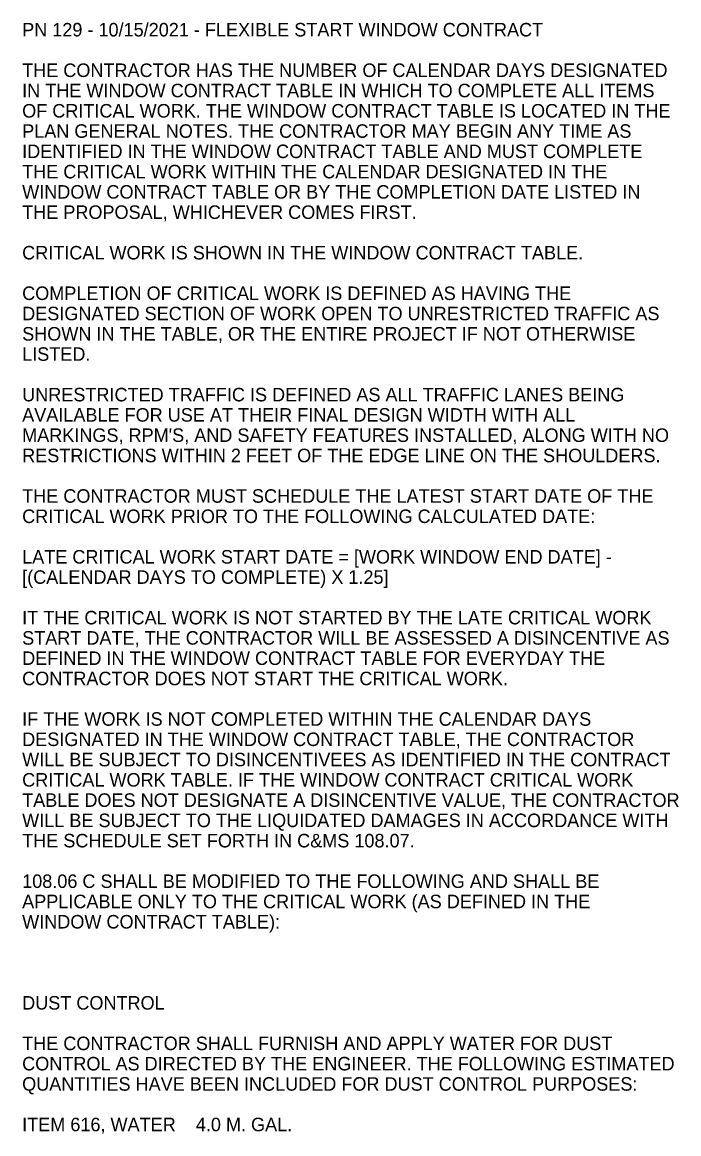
# Model space of a CAD drawing. Extents: x -6.4 to 60.5, y 0 to 37.1.
# Drawn here: x 37.12 to 43.92, y 25.61 to 37.13 of the extents above; entities that cross this region are included whole.
import ezdxf

# ---------------------------------------------------------------- set-up
doc = ezdxf.new("R2010")
doc.units = 0
doc.layers.add('SH_Text', color=7, linetype='Continuous')

msp = doc.modelspace()

# ---------------------------------------------------------------- texts
at = {"layer": 'SH_Text'}
for s, p in [('PN 129 - 10/15/2021 - FLEXIBLE START WINDOW CONTRACT', (37.115, 36.979)), ('THE CONTRACTOR HAS THE NUMBER OF CALENDAR DAYS DESIGNATED ', (37.115, 36.559)), ('IN THE WINDOW CONTRACT TABLE IN WHICH TO COMPLETE ALL ITEMS ', (37.115, 36.349)), ('OF CRITICAL WORK. THE WINDOW CONTRACT TABLE IS LOCATED IN THE ', (37.115, 36.139)), ('PLAN GENERAL NOTES. THE CONTRACTOR MAY BEGIN ANY TIME AS ', (37.115, 35.929)), ('IDENTIFIED IN THE WINDOW CONTRACT TABLE AND MUST COMPLETE ', (37.115, 35.719)), ('THE CRITICAL WORK WITHIN THE CALENDAR DESIGNATED IN THE ', (37.115, 35.509)), ('WINDOW CONTRACT TABLE OR BY THE COMPLETION DATE LISTED IN ', (37.115, 35.299)), ('THE PROPOSAL, WHICHEVER COMES FIRST.', (37.115, 35.089)), ('CRITICAL WORK IS SHOWN IN THE WINDOW CONTRACT TABLE.', (37.115, 34.669)), ('COMPLETION OF CRITICAL WORK IS DEFINED AS HAVING THE ', (37.115, 34.249)), ('DESIGNATED SECTION OF WORK OPEN TO UNRESTRICTED TRAFFIC AS ', (37.115, 34.039)), ('SHOWN IN THE TABLE, OR THE ENTIRE PROJECT IF NOT OTHERWISE ', (37.115, 33.829)), ('LISTED.', (37.115, 33.619)), ('UNRESTRICTED TRAFFIC IS DEFINED AS ALL TRAFFIC LANES BEING ', (37.115, 33.199)), ('AVAILABLE FOR USE AT THEIR FINAL DESIGN WIDTH WITH ALL ', (37.115, 32.989)), ("MARKINGS, RPM'S, AND SAFETY FEATURES INSTALLED, ALONG WITH NO ", (37.115, 32.779)), ('RESTRICTIONS WITHIN 2 FEET OF THE EDGE LINE ON THE SHOULDERS.', (37.115, 32.569)), ('THE CONTRACTOR MUST SCHEDULE THE LATEST START DATE OF THE ', (37.115, 32.149)), ('CRITICAL WORK PRIOR TO THE FOLLOWING CALCULATED DATE:', (37.115, 31.939)), ('LATE CRITICAL WORK START DATE = [WORK WINDOW END DATE] - ', (37.115, 31.519)), ('[(CALENDAR DAYS TO COMPLETE) X 1.25]', (37.115, 31.309)), ('IT THE CRITICAL WORK IS NOT STARTED BY THE LATE CRITICAL WORK ', (37.115, 30.889)), ('START DATE, THE CONTRACTOR WILL BE ASSESSED A DISINCENTIVE AS ', (37.115, 30.679)), ('DEFINED IN THE WINDOW CONTRACT TABLE FOR EVERYDAY THE ', (37.115, 30.469)), ('CONTRACTOR DOES NOT START THE CRITICAL WORK.', (37.115, 30.259)), ('IF THE WORK IS NOT COMPLETED WITHIN THE CALENDAR DAYS ', (37.115, 29.839)), ('DESIGNATED IN THE WINDOW CONTRACT TABLE, THE CONTRACTOR ', (37.115, 29.629)), ('WILL BE SUBJECT TO DISINCENTIVEES AS IDENTIFIED IN THE CONTRACT ', (37.115, 29.419)), ('CRITICAL WORK TABLE. IF THE WINDOW CONTRACT CRITICAL WORK ', (37.115, 29.209)), ('TABLE DOES NOT DESIGNATE A DISINCENTIVE VALUE, THE CONTRACTOR ', (37.115, 28.999)), ('WILL BE SUBJECT TO THE LIQUIDATED DAMAGES IN ACCORDANCE WITH ', (37.115, 28.789)), ('THE SCHEDULE SET FORTH IN C&MS 108.07.', (37.115, 28.579)), ('108.06 C SHALL BE MODIFIED TO THE FOLLOWING AND SHALL BE ', (37.115, 28.159)), ('APPLICABLE ONLY TO THE CRITICAL WORK (AS DEFINED IN THE ', (37.115, 27.949)), ('WINDOW CONTRACT TABLE):', (37.115, 27.739)), ('DUST CONTROL', (37.115, 26.899)), ('THE CONTRACTOR SHALL FURNISH AND APPLY WATER FOR DUST ', (37.115, 26.479)), ('CONTROL AS DIRECTED BY THE ENGINEER. THE FOLLOWING ESTIMATED ', (37.115, 26.269)), ('QUANTITIES HAVE BEEN INCLUDED FOR DUST CONTROL PURPOSES:', (37.115, 26.059)), ('ITEM 616, WATER    4.0 M. GAL.', (37.115, 25.639))]:
    msp.add_text(s, height=0.14, dxfattribs=at).set_placement(p)

doc.saveas('drawing.dxf')
